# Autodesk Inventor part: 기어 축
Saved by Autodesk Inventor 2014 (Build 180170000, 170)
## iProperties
Created: 2026-08
Part Number: 기어 축
Material: 일반
Document SubType Name: Modeling
Designer: dg
Density: 1 g/cm^3
Appearance: 기본값
Author: dg
Author: jhkim
Creation Date: 2026-07-31
Sending System: Autodesk Inventor 2027
Preprocessor: ST-DEVELOPER v20.1
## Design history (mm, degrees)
node "기어 축1"
node "솔리드1"
node "기준1"
